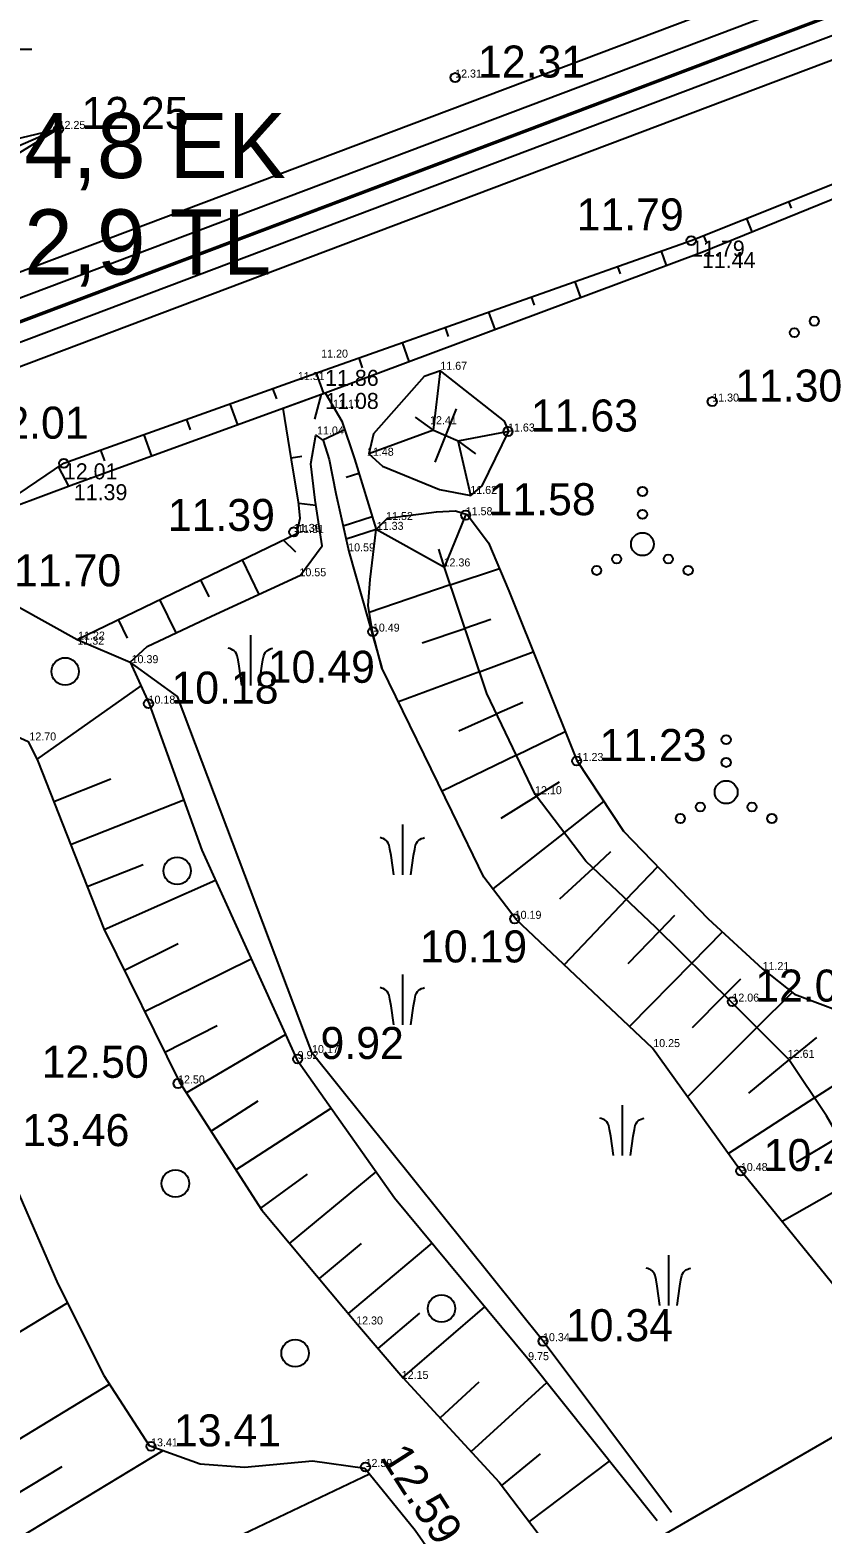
# Model space of a CAD drawing. Extents: x 433497 to 434382, y 6534486 to 6534993.
# Drawn here: x 433661.1 to 433695.8, y 6534564 to 6534629.3 of the extents above; entities that cross this region are included whole.
import ezdxf

# ---------------------------------------------------------------- set-up
doc = ezdxf.new("R2010")
doc.units = 0
for name, color, linetype in [('Default', 7, 'Continuous'), ('GEOLPUNKT', 7, 'Continuous'), ('HALJASTUS', 7, 'Continuous'), ('kataster', 7, 'Continuous'), ('KORGUS-EH2000', 7, 'Continuous'), ('MOOTKORG-EH2000', 7, 'Continuous'), ('PIIR', 7, 'Continuous'), ('RELJEEF', 7, 'Continuous'), ('VORMISTUS', 7, 'Continuous')]:
    doc.layers.add(name, color=color, linetype=linetype)

msp = doc.modelspace()

# ---------------------------------------------------------------- linework, layer by layer
at = {"layer": 'Default'}
msp.add_lwpolyline([(433617.12, 6534791.025), (433632.75, 6534606.045), (434137.38, 6534796.515), (434127.69, 6534855.6), (433968.21, 6534911.925), (433942.38, 6534904.035), (433920.99, 6534907.275)], close=True, dxfattribs=at)
msp.add_lwpolyline([(433617.12, 6534791.025), (433632.75, 6534606.045), (434137.38, 6534796.515), (434127.69, 6534855.6), (433968.21, 6534911.925), (433942.38, 6534904.035), (433920.99, 6534907.275)], close=True, dxfattribs=at)
msp.add_lwpolyline([(433617.12, 6534791.025), (433632.75, 6534606.045), (434137.38, 6534796.515), (434127.69, 6534855.6), (433968.21, 6534911.925), (433942.38, 6534904.035), (433920.99, 6534907.275)], close=True, dxfattribs=at)
at = {"layer": 'GEOLPUNKT'}
msp.add_lwpolyline([(433655.069, 6534628.467), (433661.197, 6534628.467)], dxfattribs=at)
at = {"layer": 'HALJASTUS'}
for p, q in [((433670.76, 6534602.833), (433670.76, 6534600.631)), ((433677.399, 6534594.553), (433677.399, 6534592.35)), ((433677.399, 6534587.991), (433677.399, 6534585.788)), ((433687.005, 6534582.288), (433687.005, 6534580.086)), ((433689.035, 6534575.726), (433689.035, 6534573.524))]:
    msp.add_line(p, q, dxfattribs=at)
for points in [[(433670.385, 6534600.631), (433670.267, 6534601.473), (433670.22, 6534601.755), (433670.178, 6534601.937), (433670.146, 6534602.019), (433670.099, 6534602.09), (433670.048, 6534602.142), (433669.994, 6534602.182), (433669.919, 6534602.22), (433669.855, 6534602.244), (433669.786, 6534602.263)], [(433671.135, 6534600.631), (433671.254, 6534601.473), (433671.301, 6534601.755), (433671.343, 6534601.937), (433671.375, 6534602.019), (433671.422, 6534602.09), (433671.473, 6534602.142), (433671.527, 6534602.182), (433671.602, 6534602.22), (433671.666, 6534602.244), (433671.735, 6534602.263)], [(433677.024, 6534592.35), (433676.906, 6534593.192), (433676.859, 6534593.475), (433676.816, 6534593.657), (433676.784, 6534593.739), (433676.737, 6534593.81), (433676.687, 6534593.862), (433676.632, 6534593.902), (433676.558, 6534593.94), (433676.493, 6534593.963), (433676.424, 6534593.983)], [(433677.774, 6534592.35), (433677.892, 6534593.192), (433677.939, 6534593.475), (433677.981, 6534593.657), (433678.014, 6534593.739), (433678.06, 6534593.81), (433678.111, 6534593.862), (433678.166, 6534593.902), (433678.24, 6534593.94), (433678.304, 6534593.963), (433678.373, 6534593.983)], [(433677.024, 6534585.788), (433676.906, 6534586.631), (433676.859, 6534586.913), (433676.816, 6534587.095), (433676.784, 6534587.177), (433676.737, 6534587.248), (433676.687, 6534587.3), (433676.632, 6534587.34), (433676.558, 6534587.378), (433676.493, 6534587.401), (433676.424, 6534587.421)], [(433677.774, 6534585.788), (433677.892, 6534586.631), (433677.939, 6534586.913), (433677.981, 6534587.095), (433678.014, 6534587.177), (433678.06, 6534587.248), (433678.111, 6534587.3), (433678.166, 6534587.34), (433678.24, 6534587.378), (433678.304, 6534587.401), (433678.373, 6534587.421)], [(433686.63, 6534580.086), (433686.512, 6534580.928), (433686.465, 6534581.21), (433686.422, 6534581.392), (433686.39, 6534581.474), (433686.343, 6534581.545), (433686.293, 6534581.597), (433686.238, 6534581.637), (433686.164, 6534581.675), (433686.099, 6534581.699), (433686.03, 6534581.718)], [(433687.38, 6534580.086), (433687.498, 6534580.928), (433687.545, 6534581.21), (433687.587, 6534581.392), (433687.62, 6534581.474), (433687.666, 6534581.545), (433687.717, 6534581.597), (433687.772, 6534581.637), (433687.846, 6534581.675), (433687.91, 6534581.699), (433687.979, 6534581.718)], [(433688.66, 6534573.524), (433688.542, 6534574.366), (433688.495, 6534574.648), (433688.453, 6534574.83), (433688.42, 6534574.912), (433688.374, 6534574.983), (433688.323, 6534575.035), (433688.268, 6534575.075), (433688.194, 6534575.113), (433688.13, 6534575.137), (433688.061, 6534575.156)], [(433689.41, 6534573.524), (433689.529, 6534574.366), (433689.575, 6534574.648), (433689.618, 6534574.83), (433689.65, 6534574.912), (433689.697, 6534574.983), (433689.747, 6534575.035), (433689.802, 6534575.075), (433689.877, 6534575.113), (433689.941, 6534575.137), (433690.01, 6534575.156)]]:
    msp.add_lwpolyline(points, dxfattribs=at)
for centre, radius in [((433695.412, 6534616.566), 0.2), ((433694.542, 6534616.066), 0.2), ((433687.899, 6534609.115), 0.2), ((433687.899, 6534608.115), 0.2), ((433687.899, 6534606.815), 0.5), ((433686.769, 6534606.165), 0.2), ((433689.029, 6534606.165), 0.2), ((433685.899, 6534605.665), 0.2), ((433689.899, 6534605.665), 0.2), ((433662.655, 6534601.248), 0.6), ((433691.558, 6534598.268), 0.2), ((433691.558, 6534597.268), 0.2), ((433691.558, 6534595.968), 0.5), ((433690.428, 6534595.318), 0.2), ((433692.688, 6534595.318), 0.2), ((433689.558, 6534594.818), 0.2), ((433693.558, 6534594.818), 0.2), ((433667.552, 6534592.528), 0.6), ((433667.474, 6534578.857), 0.6), ((433679.114, 6534573.389), 0.6), ((433672.708, 6534571.436), 0.6)]:
    msp.add_circle(centre, radius, dxfattribs=at)
at = {"layer": 'kataster'}
msp.add_lwpolyline([(433617.102, 6534791.002), (433632.769, 6534606.029), (434137.446, 6534796.469), (434127.827, 6534855.589), (433950.026, 6534918.39)], close=True, dxfattribs=at)
at = {"layer": 'KORGUS-EH2000'}
for centre in [(433679.708, 6534627.219), (433662.367, 6534624.972), (433690.028, 6534620.089), (433690.95, 6534613.05), (433682.02, 6534611.74), (433662.599, 6534610.349), (433680.17, 6534608.08), (433672.65, 6534607.35), (433676.11, 6534602.99), (433666.3, 6534599.84), (433685.02, 6534597.33), (433682.31, 6534590.43), (433691.83, 6534586.81), (433672.82, 6534584.3), (433667.59, 6534583.23), (433692.2, 6534579.4), (433683.55, 6534571.96), (433666.41, 6534567.36), (433675.79, 6534566.46)]:
    msp.add_circle(centre, 0.2, dxfattribs=at)
at = {"layer": 'PIIR'}
for points in [[(433632.021, 6534604.835), (434138.248, 6534795.936), (434128.468, 6534856.135), (433968.226, 6534912.818), (433942.33, 6534904.85), (433920.952, 6534908.165), (433616.327, 6534791.524), (433632.021, 6534604.835)], [(433632.732, 6534605.959), (434137.353, 6534796.454), (434127.754, 6534855.539), (433968.208, 6534911.976), (433942.39, 6534904.031), (433921.04, 6534907.341), (433617.174, 6534790.992), (433632.732, 6534605.959)], [(433633.446, 6534604.304), (434134.891, 6534793.6)]]:
    msp.add_lwpolyline(points, dxfattribs=at)
for points in [[(433618.234, 6534790.327), (433921.149, 6534906.313), (433942.464, 6534903.008), (433968.187, 6534910.923), (434126.862, 6534854.794), (434136.235, 6534797.101), (433633.617, 6534607.362)], [(433619.24, 6534789.695), (433634.52, 6534608.851), (434135.141, 6534797.808), (434125.908, 6534854.108), (433968.165, 6534909.82), (433942.53, 6534901.99), (433921.212, 6534905.219)], [(433619.24, 6534789.695), (433634.52, 6534608.851), (434135.141, 6534797.808), (434125.908, 6534854.108), (433968.165, 6534909.82), (433942.53, 6534901.99), (433921.212, 6534905.219)]]:
    msp.add_lwpolyline(points, close=True, dxfattribs=at)
at = {"layer": 'RELJEEF'}
for p, q in [((433662.367, 6534624.972), (433662.367, 6534624.972)), ((433694.418, 6534621.51), (433694.304, 6534621.795)), ((433692.446, 6534621.054), (433692.678, 6534620.474)), ((433690.703, 6534620.016), (433690.589, 6534620.313)), ((433688.712, 6534619.624), (433688.935, 6534619.005)), ((433686.942, 6534618.63), (433686.826, 6534618.958)), ((433684.94, 6534618.292), (433685.184, 6534617.601)), ((433683.182, 6534617.263), (433683.054, 6534617.626)), ((433681.168, 6534616.959), (433681.437, 6534616.2)), ((433679.423, 6534615.896), (433679.283, 6534616.293)), ((433677.397, 6534615.627), (433677.69, 6534614.798)), ((433675.664, 6534614.529), (433675.511, 6534614.961)), ((433673.626, 6534614.293), (433673.945, 6534613.397)), ((433678.757, 6534611.792), (433679.073, 6534614.4)), ((433671.904, 6534613.168), (433671.743, 6534613.62)), ((433669.859, 6534612.946), (433670.186, 6534612.033)), ((433673.571, 6534612.277), (433673.867, 6534613.369)), ((433668.141, 6534611.811), (433667.976, 6534612.272)), ((433678.757, 6534611.792), (433677.98, 6534612.368)), ((433679.297, 6534611.563), (433679.761, 6534612.729)), ((433666.093, 6534611.599), (433666.426, 6534610.668)), ((433674.882, 6534611.817), (433673.918, 6534611.357)), ((433678.757, 6534611.792), (433675.928, 6534610.759)), ((433678.757, 6534611.792), (433679.838, 6534611.334)), ((433678.834, 6534610.398), (433679.297, 6534611.563)), ((433679.838, 6534611.334), (433682.052, 6534611.752)), ((433664.387, 6534610.458), (433664.21, 6534610.925)), ((433680.397, 6534608.938), (433679.838, 6534611.334)), ((433680.615, 6534610.759), (433679.838, 6534611.334)), ((433673.004, 6534610.651), (433672.541, 6534610.575)), ((433662.36, 6534610.187), (433662.803, 6534609.35)), ((433674.942, 6534609.739), (433675.495, 6534609.914)), ((433672.869, 6534608.602), (433673.622, 6534608.513)), ((433676.087, 6534608.003), (433674.813, 6534607.608)), ((433679.238, 6534605.793), (433680.17, 6534608.08)), ((433672.745, 6534606.468), (433672.19, 6534606.996)), ((433676.259, 6534607.448), (433674.939, 6534607.039)), ((433679.238, 6534605.793), (433676.259, 6534607.448)), ((433679.238, 6534605.793), (433679.002, 6534606.591)), ((433670.389, 6534606.127), (433671.118, 6534604.616)), ((433679.497, 6534605.028), (433681.643, 6534605.752)), ((433668.945, 6534604.517), (433668.588, 6534605.257)), ((433679.497, 6534605.028), (433675.954, 6534603.831)), ((433666.787, 6534604.388), (433667.491, 6534602.929)), ((433665.376, 6534602.71), (433664.986, 6534603.518)), ((433678.262, 6534602.499), (433680.137, 6534603.133)), ((433681.273, 6534603.516), (433680.137, 6534603.133)), ((433680.777, 6534601.238), (433683.126, 6534602.11)), ((433680.777, 6534601.238), (433677.232, 6534599.922)), ((433661.415, 6534597.403), (433665.973, 6534600.618)), ((433682.67, 6534599.892), (433681.527, 6534599.388)), ((433679.868, 6534598.656), (433681.527, 6534599.388)), ((433682.389, 6534597.583), (433684.525, 6534598.616)), ((433682.389, 6534597.583), (433679.142, 6534596.013)), ((433664.657, 6534596.536), (433662.156, 6534595.545)), ((433684.262, 6534596.401), (433683.267, 6534595.788)), ((433662.889, 6534593.684), (433667.838, 6534595.635)), ((433681.722, 6534594.836), (433683.267, 6534595.788)), ((433684.477, 6534594.195), (433686.217, 6534595.565)), ((433684.477, 6534594.195), (433681.358, 6534591.741)), ((433686.504, 6534593.359), (433685.738, 6534592.649)), ((433666.068, 6534592.789), (433663.622, 6534591.824)), ((433684.291, 6534591.307), (433685.738, 6534592.649)), ((433687.189, 6534591.272), (433688.569, 6534592.724)), ((433664.358, 6534589.964), (433669.224, 6534592.123)), ((433687.189, 6534591.272), (433684.479, 6534588.422)), ((433689.304, 6534590.582), (433688.637, 6534589.892)), ((433667.602, 6534589.334), (433665.243, 6534588.17)), ((433687.271, 6534588.483), (433688.637, 6534589.892)), ((433690.062, 6534588.489), (433691.406, 6534589.854)), ((433666.128, 6534586.377), (433670.788, 6534588.676)), ((433690.062, 6534588.489), (433687.337, 6534585.723)), ((433692.183, 6534587.789), (433691.487, 6534587.086)), ((433690.094, 6534585.68), (433691.487, 6534587.086)), ((433692.903, 6534585.674), (433694.446, 6534587.215)), ((433669.297, 6534585.755), (433667.013, 6534584.583)), ((433692.903, 6534585.674), (433689.872, 6534582.645)), ((433667.952, 6534582.821), (433672.29, 6534585.367)), ((433695.516, 6534585.243), (433694.314, 6534584.257)), ((433692.552, 6534582.812), (433694.314, 6534584.257)), ((433695.428, 6534582.596), (433698.201, 6534584.384)), ((433671.085, 6534582.459), (433669.035, 6534581.139)), ((433670.117, 6534579.457), (433674.292, 6534582.145)), ((433695.428, 6534582.596), (433691.656, 6534580.163)), ((433694.633, 6534579.795), (433696.481, 6534580.897)), ((433673.238, 6534579.264), (433671.2, 6534577.776)), ((433672.472, 6534576.234), (433676.252, 6534579.372)), ((433697.476, 6534579.162), (433694.001, 6534577.192)), ((433675.595, 6534576.237), (433673.755, 6534574.699)), ((433675.038, 6534573.164), (433678.698, 6534576.251)), ((433656.215, 6534569.67), (433662.756, 6534573.639)), ((433678.144, 6534573.187), (433676.333, 6534571.641)), ((433677.418, 6534570.376), (433681.013, 6534573.457)), ((433658.29, 6534566.251), (433664.595, 6534570.076)), ((433680.748, 6534570.163), (433679.049, 6534568.602)), ((433680.402, 6534567.129), (433683.72, 6534570.152)), ((433660.205, 6534563.093), (433666.937, 6534567.178)), ((433683.42, 6534567.036), (433681.742, 6534565.645)), ((433682.952, 6534564.053), (433686.462, 6534566.72)), ((433662.505, 6534566.469), (433659.327, 6534564.541)), ((433661.925, 6534559.482), (433675.957, 6534566.164))]:
    msp.add_line(p, q, dxfattribs=at)
for points in [[(433659.047, 6534607.945), (433662.599, 6534610.349), (433674.022, 6534614.435), (433690.028, 6534620.089), (433707.718, 6534627.146), (433725.766, 6534634.115), (433743.961, 6534641.349), (433757.363, 6534645.659)], [(433659.047, 6534607.945), (433659.047, 6534607.945), (433663.033, 6534609.436), (433674.026, 6534613.427), (433690.499, 6534619.59), (433707.686, 6534626.561), (433726.101, 6534633.687), (433744.046, 6534640.464), (433757.363, 6534645.659)], [(433627.532, 6534607.425), (433628.904, 6534609.813), (433637.2, 6534615.091), (433645.891, 6534619.186), (433655.745, 6534623.4), (433662.367, 6534624.972), (433653.734, 6534619.684), (433659.036, 6534611.145), (433659.823, 6534608.843)], [(433662.367, 6534624.972), (433650.426, 6534619.803), (433644.248, 6534617.069), (433639.403, 6534613.504), (433633.711, 6534610.042), (433629.25, 6534607.904), (433629.91, 6534604.493)], [(433663.185, 6534602.649), (433663.185, 6534602.649), (433663.185, 6534602.649), (433672.784, 6534607.283), (433672.938, 6534607.95), (433672.861, 6534608.669), (433672.626, 6534610.048), (433672.187, 6534612.759), (433674.026, 6534613.427), (433674.76, 6534612.189), (433675.301, 6534610.54), (433676.259, 6534607.448)], [(433665.502, 6534601.656), (433666.243, 6534602.344), (433669.058, 6534603.663), (433672.949, 6534605.462), (433673.887, 6534606.739), (433673.588, 6534608.739), (433673.4, 6534610.321), (433673.611, 6534611.586), (433673.942, 6534611.34), (433674.193, 6534610.512), (433674.497, 6534609.035), (433675.06, 6534606.496), (433676.508, 6534601.405)], [(433659.823, 6534608.843), (433659.047, 6534607.945), (433659.709, 6534605.462), (433658.398, 6534601.819), (433657.888, 6534600.402), (433657.888, 6534599.008), (433655.406, 6534594.208), (433655.406, 6534594.208), (433659.709, 6534580.471), (433662.338, 6534574.474), (433664.343, 6534570.464), (433666.329, 6534567.396), (433668.56, 6534566.593), (433670.496, 6534566.455), (433673.468, 6534566.731), (433675.763, 6534566.403)], [(433659.823, 6534608.843), (433659.047, 6534607.945), (433659.709, 6534605.462), (433658.398, 6534601.819), (433657.888, 6534600.402), (433657.888, 6534599.008), (433655.406, 6534594.208), (433655.406, 6534594.208), (433659.709, 6534580.471), (433662.338, 6534574.474), (433664.343, 6534570.464), (433666.329, 6534567.396), (433668.56, 6534566.593), (433670.496, 6534566.455), (433673.468, 6534566.731), (433675.763, 6534566.403)], [(433701.912, 6534574.844), (433700.967, 6534573.735), (433699.595, 6534573.024), (433698.448, 6534572.977), (433697.113, 6534573.355), (433692.148, 6534579.478), (433688.341, 6534584.774), (433682.383, 6534590.402), (433680.967, 6534592.253), (433679.585, 6534595.107), (433676.508, 6534601.405), (433676.094, 6534602.98), (433675.906, 6534604.126), (433675.995, 6534605.263), (433676.259, 6534607.448), (433676.756, 6534607.945), (433678.894, 6534608.228), (433679.719, 6534608.273), (433680.231, 6534608.11)], [(433701.912, 6534574.844), (433700.967, 6534573.735), (433699.595, 6534573.024), (433698.448, 6534572.977), (433697.113, 6534573.355), (433692.148, 6534579.478), (433688.341, 6534584.774), (433682.383, 6534590.402), (433680.967, 6534592.253), (433679.585, 6534595.107), (433676.508, 6534601.405), (433676.094, 6534602.98), (433675.906, 6534604.126), (433675.995, 6534605.263), (433676.259, 6534607.448), (433676.756, 6534607.945), (433678.894, 6534608.228), (433679.719, 6534608.273), (433680.231, 6534608.11)], [(433680.231, 6534608.11), (433681.168, 6534606.868), (433682.06, 6534604.772), (433685.031, 6534597.353), (433687.077, 6534594.27), (433690.778, 6534590.435), (433693.141, 6534588.25), (433694.546, 6534587.136), (433696.553, 6534586.378), (433697.609, 6534585.436), (433699.875, 6534581.405), (433701.581, 6534577.327), (433701.881, 6534576.121), (433701.912, 6534574.844)], [(433680.231, 6534608.11), (433681.168, 6534606.868), (433682.06, 6534604.772), (433685.031, 6534597.353), (433687.077, 6534594.27), (433690.778, 6534590.435), (433693.141, 6534588.25), (433694.546, 6534587.136), (433696.553, 6534586.378), (433697.609, 6534585.436), (433699.875, 6534581.405), (433701.581, 6534577.327), (433701.881, 6534576.121), (433701.912, 6534574.844)], [(433699.43, 6534575.672), (433697.4, 6534579.298), (433695.951, 6534581.818), (433694.299, 6534584.278), (433691.817, 6534586.76), (433688.481, 6534590.045), (433685.427, 6534592.944), (433683.211, 6534595.863), (433681.101, 6534600.279), (433679.238, 6534605.793)], [(433699.43, 6534575.672), (433697.4, 6534579.298), (433695.951, 6534581.818), (433694.299, 6534584.278), (433691.817, 6534586.76), (433688.481, 6534590.045), (433685.427, 6534592.944), (433683.211, 6534595.863), (433681.101, 6534600.279), (433679.238, 6534605.793)], [(433659.709, 6534605.462), (433660.616, 6534604.078), (433663.185, 6534602.649), (433665.502, 6534601.656)], [(433665.502, 6534601.656), (433666.329, 6534599.835), (433668.629, 6534593.433), (433672.784, 6534584.278), (433677.063, 6534578.224), (433682.88, 6534571.203), (433688.537, 6534564.124)], [(433683.55, 6534571.96), (433673.45, 6534584.56), (433667.563, 6534600.146), (433665.56, 6534601.61), (433665.56, 6534601.61)], [(433683.55, 6534571.96), (433673.45, 6534584.56), (433667.563, 6534600.146), (433665.56, 6534601.61), (433665.56, 6534601.61)], [(433689.171, 6534564.474), (433683.55, 6534571.96), (433673.45, 6534584.56), (433667.563, 6534600.146), (433665.56, 6534601.61)], [(433658.045, 6534598.997), (433658.874, 6534598.966), (433660.046, 6534598.634), (433661.033, 6534598.18), (433661.457, 6534597.318), (433664.343, 6534589.994), (433667.653, 6534583.285), (433671.256, 6534577.689), (433675.432, 6534572.693), (433677.418, 6534570.376), (433681.626, 6534565.798), (433685.042, 6534561.302)], [(433675.763, 6534566.403), (433677.962, 6534563.689), (433681.179, 6534559.07)]]:
    msp.add_lwpolyline(points, dxfattribs=at)
msp.add_lwpolyline([(433678.35, 6534614.146), (433676.138, 6534611.639), (433675.928, 6534610.759), (433676.527, 6534610.228), (433679.024, 6534609.21), (433680.397, 6534608.938), (433680.893, 6534609.367), (433682.052, 6534611.752), (433681.86, 6534612.191), (433679.073, 6534614.4)], close=True, dxfattribs=at)
at = {"layer": 'VORMISTUS'}
msp.add_lwpolyline([(433756.833, 6534894.348), (433691.203, 6534872.087), (433653.508, 6534864.187), (433636.546, 6534862.392), (433627.673, 6534847.824), (433564.128, 6534829.695), (433582.608, 6534768.478), (433587.883, 6534751.004), (433591.763, 6534747.472), (433594.096, 6534737.418), (433589.968, 6534732.121), (433592.57, 6534706.447), (433596.133, 6534671.303), (433599.93, 6534613.558), (433630.448, 6534534.937), (433664.149, 6534549.227), (433704.536, 6534572.568), (433752.081, 6534596.222), (433789.501, 6534614.839)], dxfattribs=at)
msp.add_lwpolyline([(433756.833, 6534894.348), (433691.203, 6534872.087), (433653.508, 6534864.187), (433636.546, 6534862.392), (433627.673, 6534847.824), (433564.128, 6534829.695), (433582.608, 6534768.478), (433587.883, 6534751.004), (433591.763, 6534747.472), (433594.096, 6534737.418), (433589.968, 6534732.121), (433592.57, 6534706.447), (433596.133, 6534671.303), (433599.93, 6534613.558), (433630.448, 6534534.937), (433664.149, 6534549.227), (433704.536, 6534572.568), (433752.081, 6534596.222), (433789.501, 6534614.839)], dxfattribs=at)

# ---------------------------------------------------------------- texts
at = {"layer": 'GEOLPUNKT'}
for s, p in [('4,8 EK', (433660.867, 6534622.824)), ('2,9 TL', (433660.867, 6534618.604))]:
    msp.add_text(s, height=2.85, dxfattribs=at).set_placement(p)
at = {"layer": 'KORGUS-EH2000'}
for s, p in [('12.31', (433680.708, 6534627.219)), ('12.25', (433663.367, 6534624.972)), ('11.79', (433685.018, 6534620.533)), ('11.30', (433691.95, 6534613.05)), ('12.01', (433658.998, 6534611.427)), ('11.63', (433683.02, 6534611.74)), ('11.58', (433681.17, 6534608.08)), ('11.39', (433667.143, 6534607.391)), ('11.70', (433660.42, 6534604.97)), ('10.49', (433671.515, 6534600.752)), ('10.18', (433667.3, 6534599.84)), ('11.23', (433686.02, 6534597.33)), ('10.19', (433678.171, 6534588.523)), ('12.06', (433692.83, 6534586.81)), ('9.92', (433673.82, 6534584.3)), ('12.50', (433661.627, 6534583.477)), ('13.46', (433660.78, 6534580.49)), ('10.48', (433693.2, 6534579.4)), ('10.34', (433684.55, 6534571.96)), ('13.41', (433667.41, 6534567.36))]:
    msp.add_text(s, height=1.4, dxfattribs=at).set_placement(p)
msp.add_text('12.59', height=1.4, rotation=302.61937, dxfattribs=at).set_placement((433676.405, 6534566.88))
at = {"layer": 'MOOTKORG-EH2000'}
for s, height, p in [('12.31', 0.35, (433679.708, 6534627.219)), ('12.25', 0.35, (433662.367, 6534624.972)), ('11.79', 0.7, (433690.028, 6534619.389)), ('11.79', 0.7, (433690.028, 6534619.389)), ('11.44', 0.7, (433690.499, 6534618.89)), ('11.44', 0.7, (433690.499, 6534618.89)), ('11.20', 0.35, (433673.85, 6534614.97)), ('11.67', 0.35, (433679.06, 6534614.44)), ('11.31', 0.35, (433672.83, 6534613.99)), ('11.86', 0.7, (433674.022, 6534613.735)), ('11.86', 0.7, (433674.022, 6534613.735)), ('11.08', 0.7, (433674.026, 6534612.727)), ('11.08', 0.7, (433674.026, 6534612.727)), ('11.17', 0.35, (433674.37, 6534612.78)), ('11.30', 0.35, (433690.95, 6534613.05)), ('12.41', 0.35, (433678.61, 6534612.06)), ('11.04', 0.35, (433673.67, 6534611.61)), ('11.63', 0.35, (433682.02, 6534611.74)), ('11.48', 0.35, (433675.85, 6534610.68)), ('12.01', 0.7, (433662.599, 6534609.649)), ('12.01', 0.7, (433662.599, 6534609.649)), ('11.39', 0.7, (433663.033, 6534608.736)), ('11.39', 0.7, (433663.033, 6534608.736)), ('11.62', 0.35, (433680.37, 6534609.01)), ('11.58', 0.35, (433680.17, 6534608.08)), ('11.39', 0.35, (433672.65, 6534607.35)), ('11.39', 0.35, (433672.66, 6534607.35)), ('11.31', 0.35, (433672.8, 6534607.3)), ('11.33', 0.35, (433676.28, 6534607.44)), ('11.52', 0.35, (433676.69, 6534607.87)), ('10.59', 0.35, (433675.03, 6534606.5)), ('10.55', 0.35, (433672.9, 6534605.41)), ('12.36', 0.35, (433679.2, 6534605.84)), ('10.49', 0.35, (433676.11, 6534602.99)), ('11.32', 0.35, (433663.19, 6534602.42)), ('11.22', 0.35, (433663.22, 6534602.64)), ('10.39', 0.35, (433665.56, 6534601.61)), ('10.18', 0.35, (433666.3, 6534599.84)), ('12.70', 0.35, (433661.09, 6534598.23)), ('11.23', 0.35, (433685.02, 6534597.33)), ('12.10', 0.35, (433683.2, 6534595.88)), ('10.19', 0.35, (433682.31, 6534590.43)), ('11.21', 0.35, (433693.15, 6534588.19)), ('12.06', 0.35, (433691.83, 6534586.81)), ('10.17', 0.35, (433673.45, 6534584.56)), ('10.25', 0.35, (433688.37, 6534584.82)), ('9.92', 0.35, (433672.82, 6534584.3)), ('12.61', 0.35, (433694.25, 6534584.35)), ('12.50', 0.35, (433667.59, 6534583.23)), ('10.48', 0.35, (433692.2, 6534579.4)), ('12.30', 0.35, (433675.38, 6534572.69)), ('10.34', 0.35, (433683.55, 6534571.96)), ('9.75', 0.35, (433682.9, 6534571.13)), ('12.15', 0.35, (433677.37, 6534570.31)), ('13.41', 0.35, (433666.41, 6534567.36)), ('12.59', 0.35, (433675.79, 6534566.46))]:
    msp.add_text(s, height=height, dxfattribs=at).set_placement(p)

doc.saveas('drawing.dxf')
